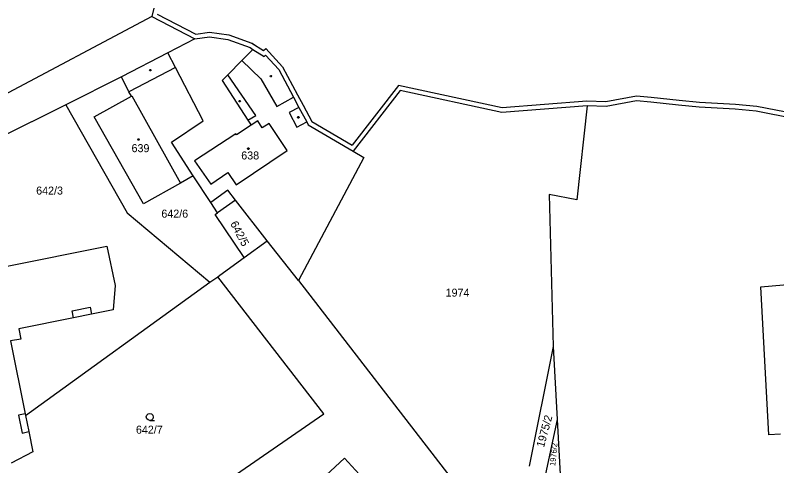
# Model space of a CAD drawing. Extents: x -621797 to -620972, y -1175539 to -1174697.
# Drawn here: x -621313.4 to -621151.7, y -1174980.1 to -1174884.4 of the extents above; entities that cross this region are included whole.
import ezdxf

# ---------------------------------------------------------------- set-up
doc = ezdxf.new("R2010")
doc.units = 0
for name, color, linetype in [('Rozvod plynu EON', 7, 'Continuous'), ('SDEL EON', 7, 'Continuous'), ('SDEL EON - popis', 7, 'Continuous'), ('Silnoproud EON', 7, 'Continuous'), ('Silnoproud EON - popis', 7, 'Continuous')]:
    doc.layers.add(name, color=color, linetype=linetype)

msp = doc.modelspace()

# ---------------------------------------------------------------- linework, layer by layer
at = {"layer": 'Rozvod plynu EON'}
for points in [[(-621284.65, -1174895.86), (-621284.56, -1174896.01), (-621284.65, -1174896.16), (-621284.83, -1174896.16), (-621284.92, -1174896.01), (-621284.83, -1174895.86)], [(-621259.04, -1174897.18), (-621258.95, -1174897.33), (-621259.04, -1174897.48), (-621259.22, -1174897.48), (-621259.31, -1174897.33), (-621259.22, -1174897.18)], [(-621265.67, -1174902.44), (-621265.58, -1174902.59), (-621265.67, -1174902.74), (-621265.85, -1174902.74), (-621265.94, -1174902.59), (-621265.85, -1174902.44)], [(-621253.22, -1174905.9), (-621253.13, -1174906.05), (-621253.22, -1174906.2), (-621253.4, -1174906.2), (-621253.49, -1174906.05), (-621253.4, -1174905.9)], [(-621287.15, -1174910.63), (-621287.06, -1174910.78), (-621287.15, -1174910.93), (-621287.33, -1174910.93), (-621287.42, -1174910.78), (-621287.33, -1174910.63)], [(-621263.82, -1174912.55), (-621263.73, -1174912.7), (-621263.82, -1174912.85), (-621264, -1174912.85), (-621264.09, -1174912.7), (-621264, -1174912.55)]]:
    msp.add_lwpolyline(points, close=True, dxfattribs=at)
at = {"layer": 'SDEL EON'}
msp.add_lwpolyline([(-621284.83, -1174970.44), (-621285.21, -1174970.34), (-621285.48, -1174970.07), (-621285.58, -1174969.7), (-621285.48, -1174969.33), (-621285.21, -1174969.06), (-621284.84, -1174968.96), (-621284.47, -1174969.06), (-621284.2, -1174969.33), (-621284.1, -1174969.71), (-621284.2, -1174970.09), (-621284.47, -1174970.36), (-621284.85, -1174970.46), (-621283.85, -1174970.46)], dxfattribs=at)
at = {"layer": 'SDEL EON - popis'}
for p, q in [((-621283.27, -1174884.1), (-621275.08, -1174888.35)), ((-621275.08, -1174888.35), (-621272.18, -1174887.97)), ((-621272.18, -1174887.97), (-621268.04, -1174888.53)), ((-621268.04, -1174888.53), (-621263.16, -1174890.28)), ((-621263.16, -1174890.28), (-621260.66, -1174891.88)), ((-621263.07, -1174890.31), (-621262.39, -1174890.78)), ((-621262.94, -1174891.61), (-621265.29, -1174893.96)), ((-621260.66, -1174891.88), (-621260.17, -1174891.45)), ((-621260.17, -1174891.45), (-621256.63, -1174895.32)), ((-621279.36, -1174895.48), (-621289.26, -1174900.64)), ((-621265.29, -1174893.96), (-621268.29, -1174896.99)), ((-621265.29, -1174893.96), (-621261.26, -1174897.87)), ((-621256.63, -1174895.32), (-621253.44, -1174901.28)), ((-621268.29, -1174896.99), (-621269.5, -1174898.22)), ((-621262.34, -1174905.63), (-621268.29, -1174896.99)), ((-621269.5, -1174898.22), (-621264.01, -1174906.66)), ((-621261.26, -1174897.87), (-621257.88, -1174903.73)), ((-621232.03, -1174899.27), (-621241.88, -1174911.96)), ((-621210, -1174904.03), (-621232.03, -1174899.27)), ((-621288.75, -1174901.55), (-621288.65, -1174901.5)), ((-621288.65, -1174901.5), (-621278.32, -1174920.02)), ((-621257.88, -1174903.73), (-621254.32, -1174901.75)), ((-621253.44, -1174901.28), (-621252.28, -1174903.46)), ((-621181.5, -1174901.55), (-621187.96, -1174902.73)), ((-621178.34, -1174901.81), (-621181.5, -1174901.55)), ((-621172.43, -1174902.45), (-621178.34, -1174901.81)), ((-621252.28, -1174903.46), (-621250.42, -1174906.92)), ((-621192.01, -1174902.62), (-621210, -1174904.03)), ((-621187.96, -1174902.73), (-621192.01, -1174902.62)), ((-621168.11, -1174902.9), (-621172.43, -1174902.45)), ((-621160.41, -1174903.3), (-621168.11, -1174902.9)), ((-621155.92, -1174903.76), (-621160.41, -1174903.3)), ((-621253.16, -1174903.93), (-621255.26, -1174905.05)), ((-621255.26, -1174905.05), (-621253.61, -1174908.15)), ((-621146.57, -1174905.58), (-621155.92, -1174903.76)), ((-621264.01, -1174906.66), (-621262.34, -1174905.63)), ((-621264.01, -1174906.66), (-621263.32, -1174907.73)), ((-621261.91, -1174906.81), (-621263.32, -1174907.73)), ((-621260.96, -1174908.31), (-621261.91, -1174906.81)), ((-621263.32, -1174907.73), (-621266.43, -1174909.78)), ((-621259.5, -1174907.36), (-621260.96, -1174908.31)), ((-621255.69, -1174913.09), (-621259.5, -1174907.36)), ((-621253.61, -1174908.15), (-621251.5, -1174907.02)), ((-621250.42, -1174906.92), (-621241.88, -1174911.96)), ((-621266.6, -1174909.53), (-621275.32, -1174915.27)), ((-621266.43, -1174909.78), (-621266.6, -1174909.53)), ((-621266.53, -1174920.42), (-621255.69, -1174913.09)), ((-621275.32, -1174915.27), (-621271.88, -1174920.22)), ((-621271.88, -1174920.22), (-621268.3, -1174917.8)), ((-621268.3, -1174917.8), (-621266.53, -1174920.42)), ((-621266.64, -1174923.61), (-621270.48, -1174926.37)), ((-621301.33, -1174947.16), (-621297.52, -1174946.37)), ((-621301.04, -1174948.61), (-621301.33, -1174947.16)), ((-621297.52, -1174946.37), (-621297.23, -1174947.84)), ((-621311.32, -1174969.03), (-621312.75, -1174969.31)), ((-621312.75, -1174969.31), (-621311.98, -1174973.11)), ((-621311.98, -1174973.11), (-621310.54, -1174972.81))]:
    msp.add_line(p, q, dxfattribs=at)
at = {"layer": 'Silnoproud EON'}
for p, q in [((-621276.36, -1174853.43), (-621284.44, -1174884.62)), ((-621284.44, -1174884.62), (-621337.73, -1174912.93)), ((-621284.44, -1174884.62), (-621275.26, -1174889.38)), ((-621275.26, -1174889.38), (-621272.18, -1174888.98)), ((-621272.18, -1174888.98), (-621268.28, -1174889.51)), ((-621275.26, -1174889.38), (-621280.99, -1174892.37)), ((-621268.28, -1174889.51), (-621263.53, -1174891.21)), ((-621263.53, -1174891.21), (-621262.94, -1174891.61)), ((-621262.94, -1174891.61), (-621260.57, -1174893.13)), ((-621280.99, -1174892.37), (-621290.83, -1174897.48)), ((-621279.36, -1174895.48), (-621280.99, -1174892.37)), ((-621260.57, -1174893.13), (-621260.25, -1174892.85)), ((-621260.25, -1174892.85), (-621257.45, -1174895.9)), ((-621273.54, -1174906.77), (-621279.36, -1174895.48)), ((-621257.45, -1174895.9), (-621254.32, -1174901.75)), ((-621290.83, -1174897.48), (-621302.7, -1174903.37)), ((-621289.26, -1174900.64), (-621290.83, -1174897.48)), ((-621231.63, -1174900.38), (-621241.63, -1174913.27)), ((-621210.07, -1174905.04), (-621231.63, -1174900.38)), ((-621296.62, -1174905.96), (-621288.75, -1174901.55)), ((-621288.75, -1174901.55), (-621289.26, -1174900.64)), ((-621254.32, -1174901.75), (-621253.16, -1174903.93)), ((-621302.7, -1174903.37), (-621330.5, -1174917.18)), ((-621302.7, -1174903.37), (-621289.64, -1174926.36)), ((-621191.98, -1174903.62), (-621210.07, -1174905.04)), ((-621191.98, -1174903.62), (-621194.14, -1174923.54)), ((-621187.88, -1174903.73), (-621191.98, -1174903.62)), ((-621181.45, -1174902.56), (-621187.88, -1174903.73)), ((-621178.43, -1174902.81), (-621181.45, -1174902.56)), ((-621172.54, -1174903.44), (-621178.43, -1174902.81)), ((-621168.19, -1174903.9), (-621172.54, -1174903.44)), ((-621253.16, -1174903.93), (-621251.5, -1174907.02)), ((-621160.49, -1174904.3), (-621168.19, -1174903.9)), ((-621156.07, -1174904.75), (-621160.49, -1174904.3)), ((-621146.73, -1174906.57), (-621156.07, -1174904.75)), ((-621286.16, -1174924.41), (-621296.62, -1174905.96)), ((-621280.25, -1174911.36), (-621273.54, -1174906.77)), ((-621251.5, -1174907.02), (-621251.17, -1174907.64)), ((-621251.17, -1174907.64), (-621241.63, -1174913.27)), ((-621275.6, -1174918.49), (-621280.25, -1174911.36)), ((-621241.63, -1174913.27), (-621239.36, -1174914.61)), ((-621239.36, -1174914.61), (-621253.29, -1174940.71)), ((-621275.6, -1174918.49), (-621278.32, -1174920.02)), ((-621271.91, -1174924.17), (-621275.6, -1174918.49)), ((-621278.32, -1174920.02), (-621286.16, -1174924.41)), ((-621268.25, -1174921.55), (-621271.91, -1174924.17)), ((-621266.64, -1174923.61), (-621268.25, -1174921.55)), ((-621194.14, -1174923.54), (-621200.05, -1174922.43)), ((-621200.05, -1174922.43), (-621199.2, -1174954.76)), ((-621270.48, -1174926.37), (-621271.91, -1174924.17)), ((-621259.88, -1174932.28), (-621266.64, -1174923.61)), ((-621289.64, -1174926.36), (-621272.07, -1174941.09)), ((-621270.96, -1174926.72), (-621270.48, -1174926.37)), ((-621264.77, -1174935.81), (-621270.96, -1174926.72)), ((-621264.77, -1174935.81), (-621259.88, -1174932.28)), ((-621253.29, -1174940.71), (-621259.88, -1174932.28)), ((-621315.48, -1174937.76), (-621293.93, -1174933.43)), ((-621293.93, -1174933.43), (-621292.22, -1174941.77)), ((-621269.99, -1174939.59), (-621264.77, -1174935.81)), ((-621272.07, -1174941.09), (-621270.42, -1174939.9)), ((-621270.42, -1174939.9), (-621269.99, -1174939.59)), ((-621247.85, -1174969.05), (-621270.42, -1174939.9)), ((-621253.29, -1174940.71), (-621206.58, -1175001.12)), ((-621311.24, -1174969.4), (-621272.07, -1174941.09)), ((-621292.22, -1174941.77), (-621292.65, -1174946.93)), ((-621155.09, -1174942.02), (-621144.12, -1174941.13)), ((-621153.35, -1174973.48), (-621155.09, -1174942.02)), ((-621292.65, -1174946.93), (-621297.23, -1174947.84)), ((-621301.04, -1174948.61), (-621312.65, -1174950.97)), ((-621297.23, -1174947.84), (-621301.04, -1174948.61)), ((-621312.65, -1174950.97), (-621312.24, -1174953.14)), ((-621312.24, -1174953.14), (-621314.39, -1174953.56)), ((-621314.39, -1174953.56), (-621311.32, -1174969.03)), ((-621199.2, -1174954.76), (-621204.28, -1174980.15)), ((-621199.2, -1174954.76), (-621198.35, -1174970.23)), ((-621311.32, -1174969.03), (-621311.24, -1174969.4)), ((-621311.24, -1174969.4), (-621310.54, -1174972.81)), ((-621305.54, -1175008.66), (-621247.85, -1174969.05)), ((-621198.35, -1174970.23), (-621200.83, -1174981.75)), ((-621198.35, -1174970.23), (-621197.63, -1174983.23)), ((-621310.54, -1174972.81), (-621309.68, -1174977.09)), ((-621150.91, -1174973.34), (-621153.35, -1174973.48)), ((-621309.68, -1174977.09), (-621314.28, -1174979.48)), ((-621243.52, -1174978.48), (-621251.59, -1174985.95)), ((-621240.39, -1174981.87), (-621243.52, -1174978.48))]:
    msp.add_line(p, q, dxfattribs=at)

# ---------------------------------------------------------------- texts
at = {"layer": 'Silnoproud EON - popis'}
for s, p in [('639', (-621288.713, -1174913.45)), ('638', (-621265.413, -1174915)), ('642/3', (-621308.973, -1174922.46)), ('642/6', (-621282.383, -1174927.36)), ('1974', (-621222.007, -1174944.14)), ('642/7', (-621287.783, -1174973.25))]:
    msp.add_text(s, height=1.7, dxfattribs=at).set_placement(p)
for s, height, rotation, p in [('642/5', 1.7, 297.88076, (-621267.813, -1174928.616)), ('1975/2', 1.7, 74.7137, (-621201.136, -1174976.291)), ('1976/2', 1.2, 84.62587, (-621198.724, -1174980.164))]:
    msp.add_text(s, height=height, rotation=rotation, dxfattribs=at).set_placement(p)

doc.saveas('drawing.dxf')
